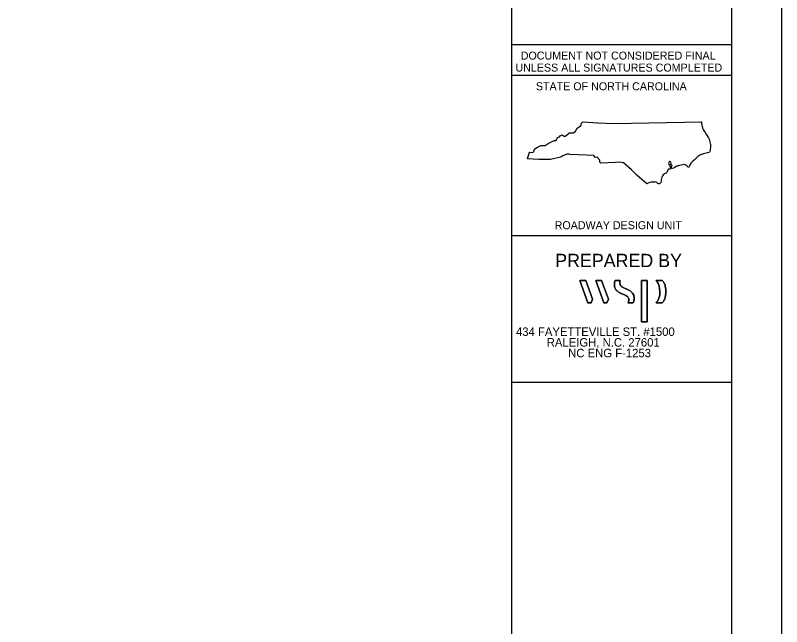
# Model space of a CAD drawing. Extents: x 1844369 to 1844800, y 671424 to 671721.
# Drawn here: x 1844552.92 to 1844581.79, y 671547.07 to 671570.09 of the extents above; entities that cross this region are included whole.
import ezdxf

# ---------------------------------------------------------------- set-up
doc = ezdxf.new("R2010")
doc.units = 0
for name, color, linetype in [('Old_Level_1', 7, 'Continuous'), ('Prop DSN Text', 7, 'Continuous'), ('Sheet Plan CELL', 7, 'Continuous'), ('Sheet Title CELL', 7, 'Continuous'), ('Sheet_Clip_Boundary_CELL', 7, 'Continuous'), ('Sheet_Plan_CELL', 7, 'Continuous')]:
    doc.layers.add(name, color=color, linetype=linetype)

msp = doc.modelspace()

# ---------------------------------------------------------------- linework, layer by layer
at = {"layer": 'Old_Level_1'}
msp.add_line((1844578.765, 671566.082), (1844578.764, 671566.086), dxfattribs=at)
for points in [[(1844572.217, 671564.693), (1844572.269, 671564.9), (1844572.301, 671564.937), (1844572.411, 671564.929), (1844572.449, 671564.966), (1844572.479, 671565.047), (1844572.561, 671565.112), (1844572.715, 671565.183), (1844572.878, 671565.185), (1844572.993, 671565.266), (1844573.147, 671565.335), (1844573.223, 671565.376), (1844573.298, 671565.379), (1844573.348, 671565.492), (1844573.421, 671565.513), (1844573.445, 671565.553), (1844573.524, 671565.59), (1844573.595, 671565.537), (1844573.634, 671565.541), (1844573.678, 671565.582), (1844573.794, 671565.666), (1844573.951, 671565.668), (1844574.022, 671565.729), (1844574.083, 671565.843), (1844574.161, 671565.897), (1844574.232, 671565.953), (1844574.248, 671566.029), (1844574.294, 671566.086)], [(1844574.294, 671566.086), (1844574.861, 671566.045), (1844575.486, 671566.021), (1844576.135, 671566.029), (1844576.798, 671566.041), (1844577.449, 671566.052), (1844578.123, 671566.072), (1844578.746, 671566.086), (1844578.764, 671566.086)], [(1844576.71, 671563.747), (1844576.325, 671564.066), (1844576.13, 671564.27), (1844575.829, 671564.533), (1844575.674, 671564.558), (1844575.51, 671564.55), (1844574.972, 671564.523), (1844574.941, 671564.563), (1844574.941, 671564.603), (1844574.938, 671564.643), (1844574.839, 671564.753), (1844574.763, 671564.743), (1844574.71, 671564.818), (1844574.434, 671564.825), (1844573.81, 671564.854), (1844573.771, 671564.861), (1844573.697, 671564.861), (1844573.542, 671564.806), (1844573.468, 671564.746), (1844573.239, 671564.698), (1844573.077, 671564.66), (1844572.642, 671564.666), (1844572.217, 671564.693)]]:
    msp.add_lwpolyline(points, dxfattribs=at)
for points in [[(1844578.765, 671566.082), (1844578.774, 671565.96), (1844579.003, 671565.519), (1844579.086, 671565.324), (1844579.104, 671565.123), (1844579.094, 671564.993)], [(1844579.094, 671564.993), (1844579.075, 671564.952), (1844579.039, 671564.931), (1844578.845, 671564.877)], [(1844578.845, 671564.877), (1844578.703, 671564.82), (1844578.443, 671564.594), (1844578.342, 671564.482), (1844578.292, 671564.367), (1844578.181, 671564.453), (1844577.943, 671564.431), (1844577.857, 671564.419), (1844577.667, 671564.329), (1844577.631, 671564.356), (1844577.629, 671564.393), (1844577.661, 671564.43), (1844577.606, 671564.498), (1844577.62, 671564.534), (1844577.557, 671564.587), (1844577.535, 671564.55), (1844577.536, 671564.472), (1844577.572, 671564.437), (1844577.57, 671564.399), (1844577.618, 671564.323), (1844577.493, 671564.276), (1844577.479, 671564.194), (1844577.363, 671564.115), (1844577.26, 671563.951), (1844577.199, 671563.759), (1844577.162, 671563.741), (1844577.088, 671563.801), (1844576.963, 671563.81), (1844576.926, 671563.811), (1844576.71, 671563.747)]]:
    msp.add_spline(points, degree=3, dxfattribs=at)
at = {"layer": 'Prop DSN Text'}
for p, q in [((1844574.487, 671559.265), (1844574.18, 671560.107)), ((1844574.18, 671560.107), (1844574.404, 671560.107)), ((1844574.404, 671560.107), (1844574.659, 671559.409)), ((1844575.088, 671559.265), (1844574.781, 671560.107)), ((1844574.781, 671560.107), (1844575.005, 671560.107)), ((1844575.005, 671560.107), (1844575.26, 671559.409)), ((1844576.502, 671558.551), (1844576.502, 671560.107)), ((1844576.502, 671560.107), (1844576.716, 671560.107)), ((1844576.716, 671560.107), (1844576.716, 671558.551)), ((1844574.606, 671559.265), (1844574.487, 671559.265)), ((1844574.659, 671559.409), (1844574.606, 671559.265)), ((1844575.207, 671559.265), (1844575.088, 671559.265)), ((1844575.26, 671559.409), (1844575.207, 671559.265)), ((1844576.716, 671558.551), (1844576.502, 671558.551))]:
    msp.add_line(p, q, dxfattribs=at)
for points in [[(1844574.404, 671560.107), (1844574.18, 671560.107), (1844574.487, 671559.265), (1844574.606, 671559.265), (1844574.659, 671559.409), (1844574.404, 671560.107)], [(1844575.005, 671560.107), (1844574.781, 671560.107), (1844575.088, 671559.265), (1844575.207, 671559.265), (1844575.26, 671559.409), (1844575.005, 671560.107)], [(1844576.716, 671558.551), (1844576.716, 671560.107), (1844576.502, 671560.107), (1844576.502, 671558.551), (1844576.716, 671558.551)]]:
    msp.add_lwpolyline(points, dxfattribs=at)
for points in [[(1844575.487, 671559.982), (1844575.491, 671560.025), (1844575.499, 671560.068), (1844575.516, 671560.107), (1844575.516, 671560.107), (1844575.712, 671560.107), (1844575.712, 671560.107), (1844575.696, 671560.077), (1844575.681, 671560.023), (1844575.698, 671559.968), (1844575.714, 671559.92), (1844575.747, 671559.886), (1844575.79, 671559.859), (1844575.84, 671559.826), (1844575.898, 671559.808), (1844575.952, 671559.783), (1844576.008, 671559.756), (1844576.063, 671559.729), (1844576.11, 671559.688), (1844576.178, 671559.628), (1844576.22, 671559.556), (1844576.227, 671559.465), (1844576.227, 671559.454), (1844576.228, 671559.443), (1844576.228, 671559.432), (1844576.228, 671559.374), (1844576.219, 671559.317), (1844576.193, 671559.265), (1844576.193, 671559.265), (1844575.992, 671559.265), (1844575.992, 671559.265), (1844576.012, 671559.299), (1844576.027, 671559.345), (1844576.025, 671559.388), (1844576.018, 671559.494), (1844575.889, 671559.552), (1844575.782, 671559.601), (1844575.765, 671559.608), (1844575.749, 671559.615), (1844575.734, 671559.622), (1844575.687, 671559.645), (1844575.64, 671559.67), (1844575.6, 671559.704), (1844575.558, 671559.739), (1844575.527, 671559.774), (1844575.507, 671559.825), (1844575.49, 671559.87), (1844575.484, 671559.919), (1844575.486, 671559.967), (1844575.487, 671559.972), (1844575.487, 671559.977), (1844575.487, 671559.982)], [(1844575.487, 671559.982), (1844575.487, 671559.977), (1844575.487, 671559.972), (1844575.486, 671559.967), (1844575.484, 671559.919), (1844575.49, 671559.87), (1844575.507, 671559.825), (1844575.527, 671559.774), (1844575.558, 671559.739), (1844575.6, 671559.704), (1844575.64, 671559.67), (1844575.687, 671559.645), (1844575.734, 671559.622), (1844575.749, 671559.615), (1844575.765, 671559.608), (1844575.782, 671559.601), (1844575.889, 671559.552), (1844576.018, 671559.494), (1844576.025, 671559.388), (1844576.027, 671559.345), (1844576.012, 671559.299), (1844575.992, 671559.265), (1844575.992, 671559.265), (1844576.193, 671559.265), (1844576.193, 671559.265), (1844576.219, 671559.317), (1844576.228, 671559.374), (1844576.228, 671559.432), (1844576.228, 671559.443), (1844576.227, 671559.454), (1844576.227, 671559.465), (1844576.22, 671559.556), (1844576.178, 671559.628), (1844576.11, 671559.688), (1844576.063, 671559.729), (1844576.008, 671559.756), (1844575.952, 671559.783), (1844575.898, 671559.808), (1844575.84, 671559.826), (1844575.79, 671559.859), (1844575.747, 671559.886), (1844575.714, 671559.92), (1844575.698, 671559.968), (1844575.681, 671560.023), (1844575.696, 671560.077), (1844575.712, 671560.107), (1844575.712, 671560.107), (1844575.516, 671560.107), (1844575.516, 671560.107), (1844575.499, 671560.068), (1844575.491, 671560.025), (1844575.487, 671559.982)], [(1844577.196, 671559.687), (1844577.196, 671559.863), (1844577.132, 671560.01), (1844577.048, 671560.107), (1844577.048, 671560.107), (1844577.291, 671560.107), (1844577.291, 671560.107), (1844577.371, 671560.009), (1844577.42, 671559.842), (1844577.42, 671559.687), (1844577.42, 671559.687), (1844577.42, 671559.686), (1844577.42, 671559.686), (1844577.42, 671559.53), (1844577.371, 671559.363), (1844577.291, 671559.265), (1844577.291, 671559.265), (1844577.048, 671559.265), (1844577.048, 671559.265), (1844577.132, 671559.362), (1844577.196, 671559.509), (1844577.196, 671559.686), (1844577.196, 671559.686), (1844577.196, 671559.687), (1844577.196, 671559.687)], [(1844577.196, 671559.687), (1844577.196, 671559.687), (1844577.196, 671559.686), (1844577.196, 671559.686), (1844577.196, 671559.509), (1844577.132, 671559.362), (1844577.048, 671559.265), (1844577.048, 671559.265), (1844577.291, 671559.265), (1844577.291, 671559.265), (1844577.371, 671559.363), (1844577.42, 671559.53), (1844577.42, 671559.686), (1844577.42, 671559.686), (1844577.42, 671559.687), (1844577.42, 671559.687), (1844577.42, 671559.842), (1844577.371, 671560.009), (1844577.291, 671560.107), (1844577.291, 671560.107), (1844577.048, 671560.107), (1844577.048, 671560.107), (1844577.132, 671560.01), (1844577.196, 671559.863), (1844577.196, 671559.687)]]:
    msp.add_open_spline(points, degree=3, dxfattribs=at)
at = {"layer": 'Sheet Plan CELL'}
for p, q in [((1844579.905, 671568.973), (1844571.617, 671568.973)), ((1844579.905, 671567.819), (1844571.617, 671567.819)), ((1844579.905, 671561.794), (1844571.617, 671561.794)), ((1844579.905, 671556.272), (1844571.617, 671556.272))]:
    msp.add_line(p, q, dxfattribs=at)
at = {"layer": 'Sheet_Clip_Boundary_CELL'}
msp.add_lwpolyline([(1844581.788, 671593.106), (1844440.123, 671593.106), (1844440.123, 671501.068), (1844581.788, 671501.068)], close=True, dxfattribs=at)
at = {"layer": 'Sheet_Plan_CELL'}
for p, q in [((1844571.615, 671502.951), (1844571.617, 671591.223)), ((1844579.903, 671502.951), (1844579.905, 671591.223))]:
    msp.add_line(p, q, dxfattribs=at)

# ---------------------------------------------------------------- texts
at = {"layer": 'Prop DSN Text'}
for s, height, p in [('DOCUMENT NOT CONSIDERED FINAL', 0.30122, (1844571.958, 671568.423)), ('UNLESS ALL SIGNATURES COMPLETED', 0.30122, (1844571.757, 671567.971)), ('STATE OF NORTH CAROLINA', 0.30122, (1844572.528, 671567.268)), ('ROADWAY DESIGN UNIT', 0.30122, (1844573.236, 671562.037)), ('PREPARED BY', 0.50203, (1844573.256, 671560.609))]:
    msp.add_text(s, height=height, dxfattribs=at).set_placement(p)
at = {"layer": 'Sheet Title CELL'}
for s, p in [('434 FAYETTEVILLE ST. #1500', (1844571.779, 671558.02)), ('RALEIGH, N.C. 27601', (1844572.938, 671557.618)), ('NC ENG F-1253', (1844573.745, 671557.216))]:
    msp.add_text(s, height=0.318, rotation=360, dxfattribs=at).set_placement(p)

doc.saveas('drawing.dxf')
